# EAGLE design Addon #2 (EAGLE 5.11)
COPYRIGHT: © 2013 Leo-Andres Hofmann; LICENSE: CC-BY-SA 3.0; PROJEKT: miniSTK Addon #2; REVISION: 1.0; TEXT-1: Pin-Breakout, Allgemeines; TEXT-2: Pufferelkos; TEXT-3: Spannungsregler (linear); TEXT-5: Platine: 75mm x 85mm; TP_SIGNAL_NAME: GND

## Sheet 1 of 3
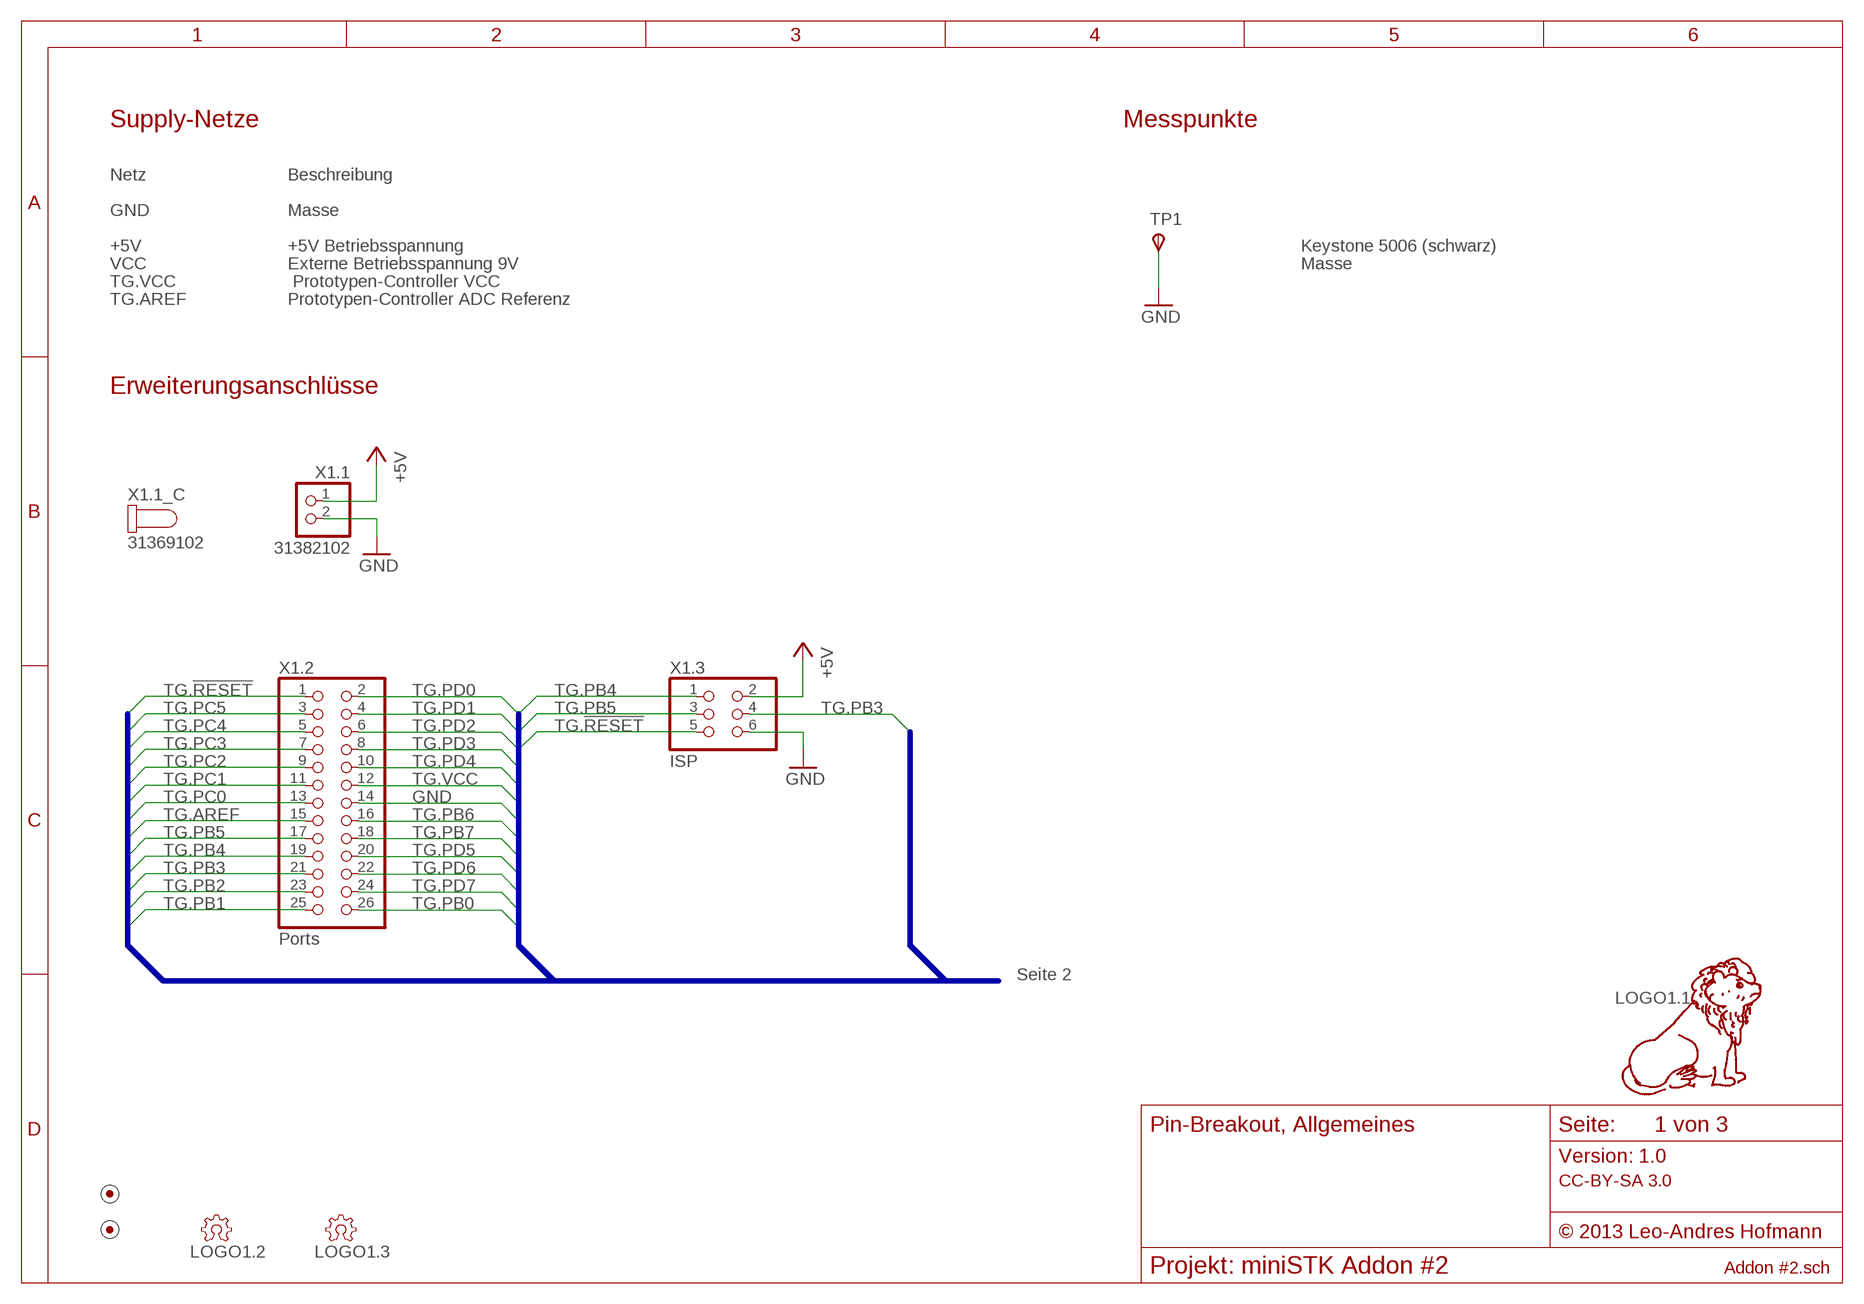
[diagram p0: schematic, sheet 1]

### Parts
LOGO1.1  LOGO-10MM-TPLACE  [10MM-TPLACE]
LOGO1.2  OSHW-3MM-FILL-TPLACE  [OSHW-FILL-3MM-TPLACE]
LOGO1.3  OSHW-3MM-FILL-TSTOP  [OSHW-FILL-3MM-TSTOP]
MARK1  FIDUCIAL-1.0/CREAM  [FIDUCIAL-1MM/CREAM]
MARK2  FIDUCIAL-1.0/CREAM  [FIDUCIAL-1MM/CREAM]
TP1  5006  TESTPOINT-1.6MM  [TESTPOINT-1.6MM]
X1.1  31382102  1PIN-2-31382102  [31382102]
X1.2  Ports  PINHD-2X13  [2X13]
X1.3  ISP  PINHD-2X3  [2X03]

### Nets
+5V: X1.1.1 X1.3.2 ; also sheet 2,3
GND: TP1.TP(PP) X1.1.2 X1.2.14 X1.3.6 ; also sheet 2,3
TG.!RESET: X1.2.1 X1.3.5 ; also sheet 2
TG.AREF: X1.2.15 ; also sheet 2
TG.PB0: X1.2.26 ; also sheet 2
TG.PB1: X1.2.25 ; also sheet 2
TG.PB2: X1.2.23 ; also sheet 2
TG.PB3: X1.2.21 X1.3.4 ; also sheet 2
TG.PB4: X1.2.19 X1.3.1 ; also sheet 2
TG.PB5: X1.2.17 X1.3.3 ; also sheet 2
TG.PB6: X1.2.16 ; also sheet 2
TG.PB7: X1.2.18 ; also sheet 2
TG.PC0: X1.2.13 ; also sheet 2
TG.PC1: X1.2.11 ; also sheet 2
TG.PC2: X1.2.9 ; also sheet 2
TG.PC3: X1.2.7 ; also sheet 2
TG.PC4: X1.2.5 ; also sheet 2
TG.PC5: X1.2.3 ; also sheet 2
TG.PD0: X1.2.2 ; also sheet 2
TG.PD1: X1.2.4 ; also sheet 2
TG.PD2: X1.2.6 ; also sheet 2
TG.PD3: X1.2.8 ; also sheet 2
TG.PD4: X1.2.10 ; also sheet 2
TG.PD5: X1.2.20 ; also sheet 2
TG.PD6: X1.2.22 ; also sheet 2
TG.PD7: X1.2.24 ; also sheet 2
TG.VCC: X1.2.12 ; also sheet 2

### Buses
TG:GND,TG.VCC,TG.!RESET,TG.AREF,TG.PB0,TG.PB1,TG.PB2,TG.PB3,TG.PB4,TG.PB5,TG.PB6,TG.PB7,TG.PC0,TG.PC1,TG.PC2,TG.PC3,TG.PC4,TG.PC5,TG.PD0,TG.PD1,TG.PD2,TG.PD3,TG.PD4,TG.PD5,TG.PD6,TG.PD7

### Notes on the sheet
- Supply-Netze | Messpunkte
- Netz | Beschreibung
- GND | Masse
- +5V | +5V Betriebsspannung | Keystone 5006 (schwarz)
- VCC | Externe Betriebsspannung 9V | Masse
- TG.VCC | Prototypen-Controller VCC
- TG.AREF | Prototypen-Controller ADC Referenz
- Erweiterungsanschlüsse
- Seite 2

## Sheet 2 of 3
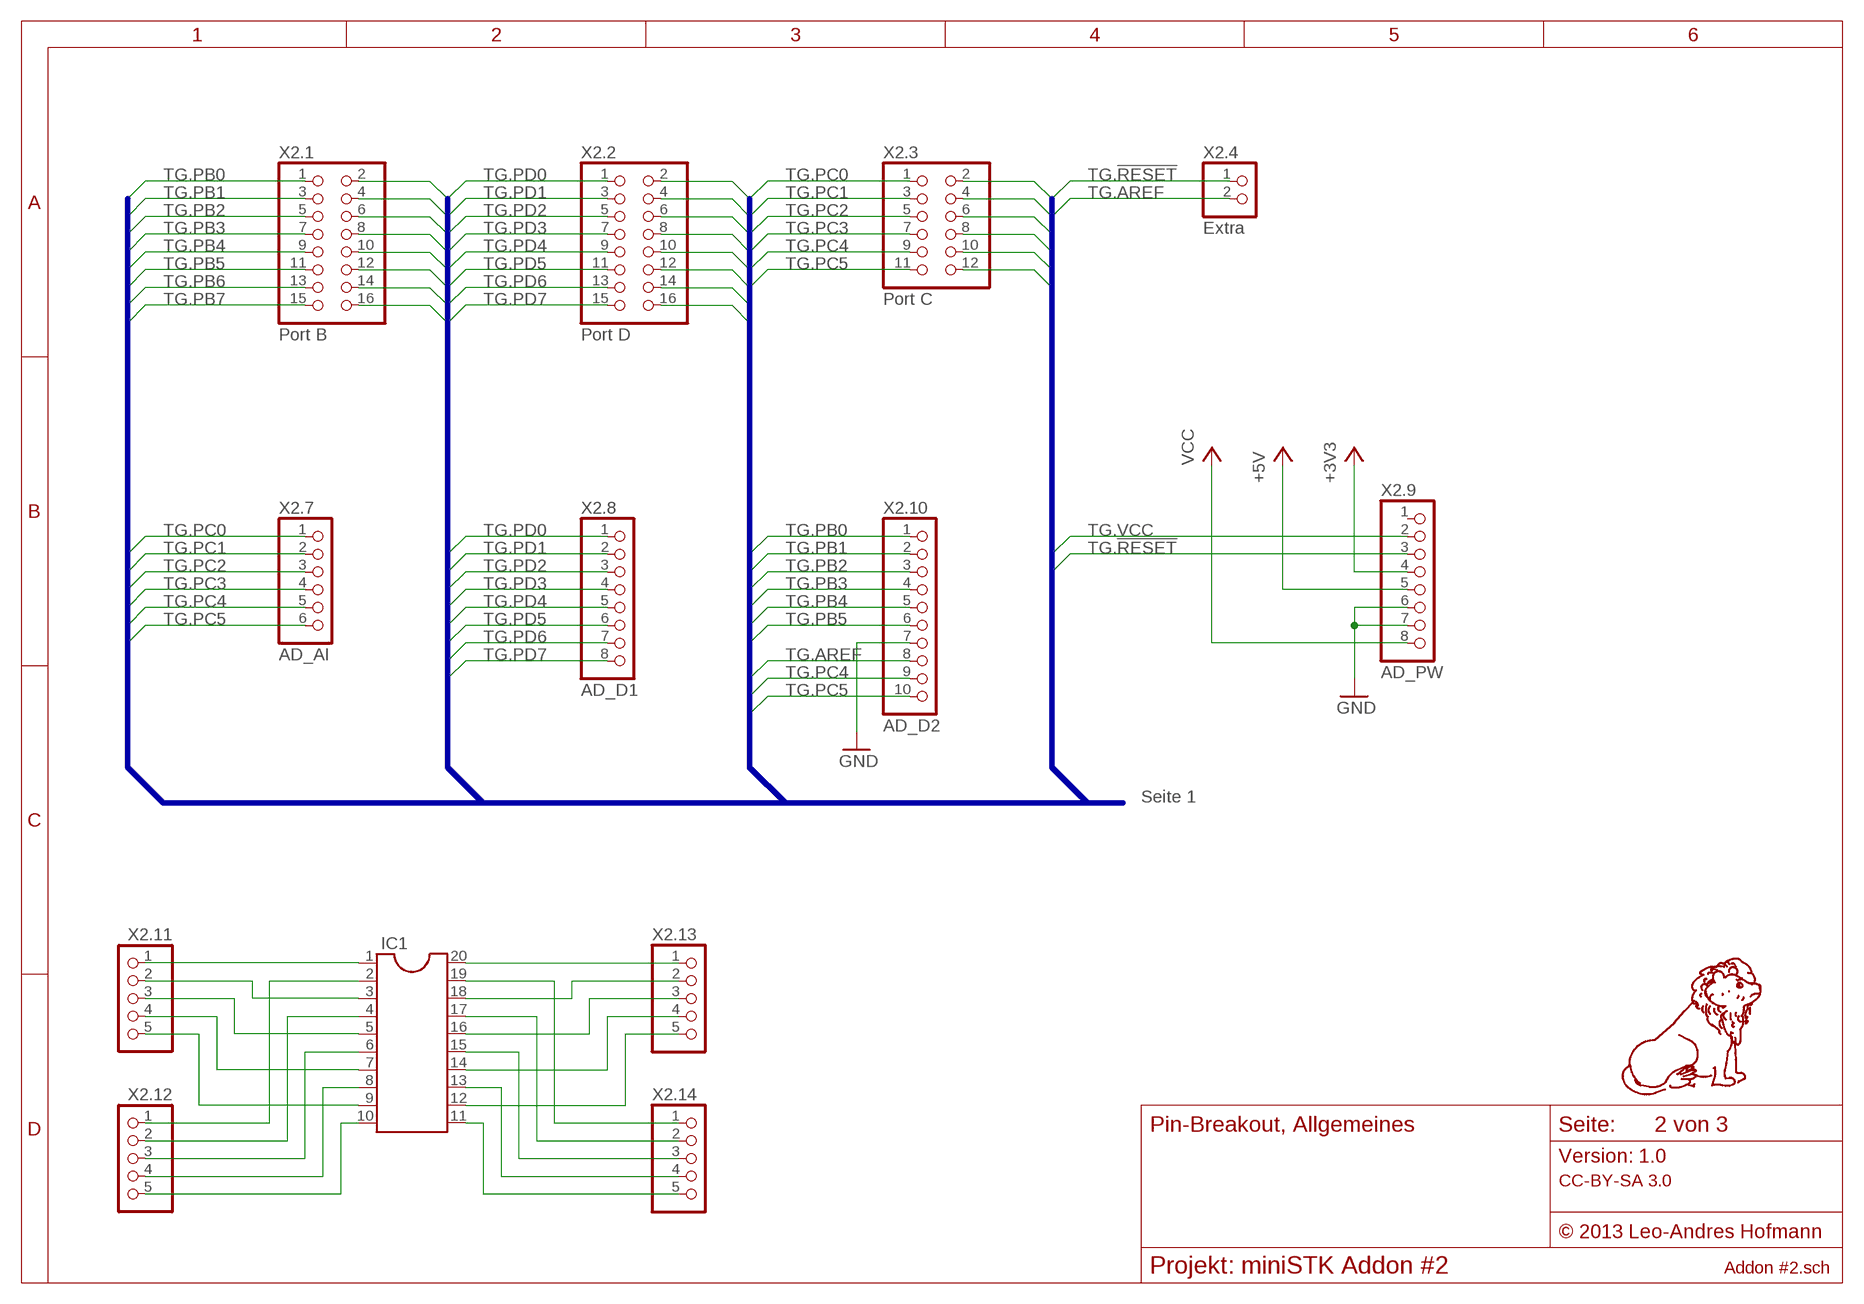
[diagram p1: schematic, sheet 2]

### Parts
IC1  SO-20  [SO-20/MULTI]
X2.1  Port B  PINHD-2X8  [2X08]
X2.2  Port D  PINHD-2X8  [2X08]
X2.3  Port C  PINHD-2X6  [2X06]
X2.4  Extra  PINHD-1X2  [1X02]
X2.7  AD_AI  PINHD-1X6  [1X06]
X2.8  AD_D1  PINHD-1X8  [1X08]
X2.9  AD_PW  PINHD-1X8  [1X08]
X2.10  AD_D2  PINHD-1X10  [1X10]
X2.11  PINHD-1X5  [1X05]
X2.12  PINHD-1X5  [1X05]
X2.13  PINHD-1X5  [1X05]
X2.14  PINHD-1X5  [1X05]

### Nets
+3V3: X2.9.4 ; also sheet 3
+5V: X2.9.5 ; also sheet 1,3
GND: X2.9.6 X2.9.7 X2.10.7 ; also sheet 1,3
N$21: IC1.1 X2.11.1
N$22: IC1.9 X2.11.5
N$23: IC1.7 X2.11.4
N$24: IC1.5 X2.11.3
N$25: IC1.3 X2.11.2
N$26: IC1.10 X2.12.5
N$27: IC1.8 X2.12.4
N$28: IC1.6 X2.12.3
N$29: IC1.4 X2.12.2
N$30: IC1.2 X2.12.1
N$31: IC1.13 X2.14.4
N$32: IC1.15 X2.14.3
N$33: IC1.20 X2.13.1
N$34: IC1.11 X2.14.5
N$35: IC1.17 X2.14.2
N$36: IC1.19 X2.14.1
N$37: IC1.12 X2.13.5
N$38: IC1.18 X2.13.2
N$39: IC1.16 X2.13.3
N$40: IC1.14 X2.13.4
TG.!RESET: X2.4.1 X2.9.3 ; also sheet 1
TG.AREF: X2.4.2 X2.10.8 ; also sheet 1
TG.PB0: X2.1.1 X2.1.2 X2.10.1 ; also sheet 1
TG.PB1: X2.1.3 X2.1.4 X2.10.2 ; also sheet 1
TG.PB2: X2.1.5 X2.1.6 X2.10.3 ; also sheet 1
TG.PB3: X2.1.7 X2.1.8 X2.10.4 ; also sheet 1
TG.PB4: X2.1.9 X2.1.10 X2.10.5 ; also sheet 1
TG.PB5: X2.1.11 X2.1.12 X2.10.6 ; also sheet 1
TG.PB6: X2.1.13 X2.1.14 ; also sheet 1
TG.PB7: X2.1.15 X2.1.16 ; also sheet 1
TG.PC0: X2.3.1 X2.3.2 X2.7.1 ; also sheet 1
TG.PC1: X2.3.3 X2.3.4 X2.7.2 ; also sheet 1
TG.PC2: X2.3.5 X2.3.6 X2.7.3 ; also sheet 1
TG.PC3: X2.3.7 X2.3.8 X2.7.4 ; also sheet 1
TG.PC4: X2.3.9 X2.3.10 X2.7.5 X2.10.9 ; also sheet 1
TG.PC5: X2.3.11 X2.3.12 X2.7.6 X2.10.10 ; also sheet 1
TG.PD0: X2.2.1 X2.2.2 X2.8.1 ; also sheet 1
TG.PD1: X2.2.3 X2.2.4 X2.8.2 ; also sheet 1
TG.PD2: X2.2.5 X2.2.6 X2.8.3 ; also sheet 1
TG.PD3: X2.2.7 X2.2.8 X2.8.4 ; also sheet 1
TG.PD4: X2.2.9 X2.2.10 X2.8.5 ; also sheet 1
TG.PD5: X2.2.11 X2.2.12 X2.8.6 ; also sheet 1
TG.PD6: X2.2.13 X2.2.14 X2.8.7 ; also sheet 1
TG.PD7: X2.2.15 X2.2.16 X2.8.8 ; also sheet 1
TG.VCC: X2.9.2 ; also sheet 1
VCC: X2.9.8 ; also sheet 3
Unconnected: X2.9.1

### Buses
PORTS:TG.VCC,TG.!RESET,TG.AREF,TG.PB0,TG.PB1,TG.PB2,TG.PB3,TG.PB4,TG.PB5,TG.PB6,TG.PB7,TG.PC0,TG.PC1,TG.PC2,TG.PC3,TG.PC4,TG.PC5,TG.PD0,TG.PD1,TG.PD2,TG.PD3,TG.PD4,TG.PD5,TG.PD6,TG.PD7

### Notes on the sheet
- Seite 1

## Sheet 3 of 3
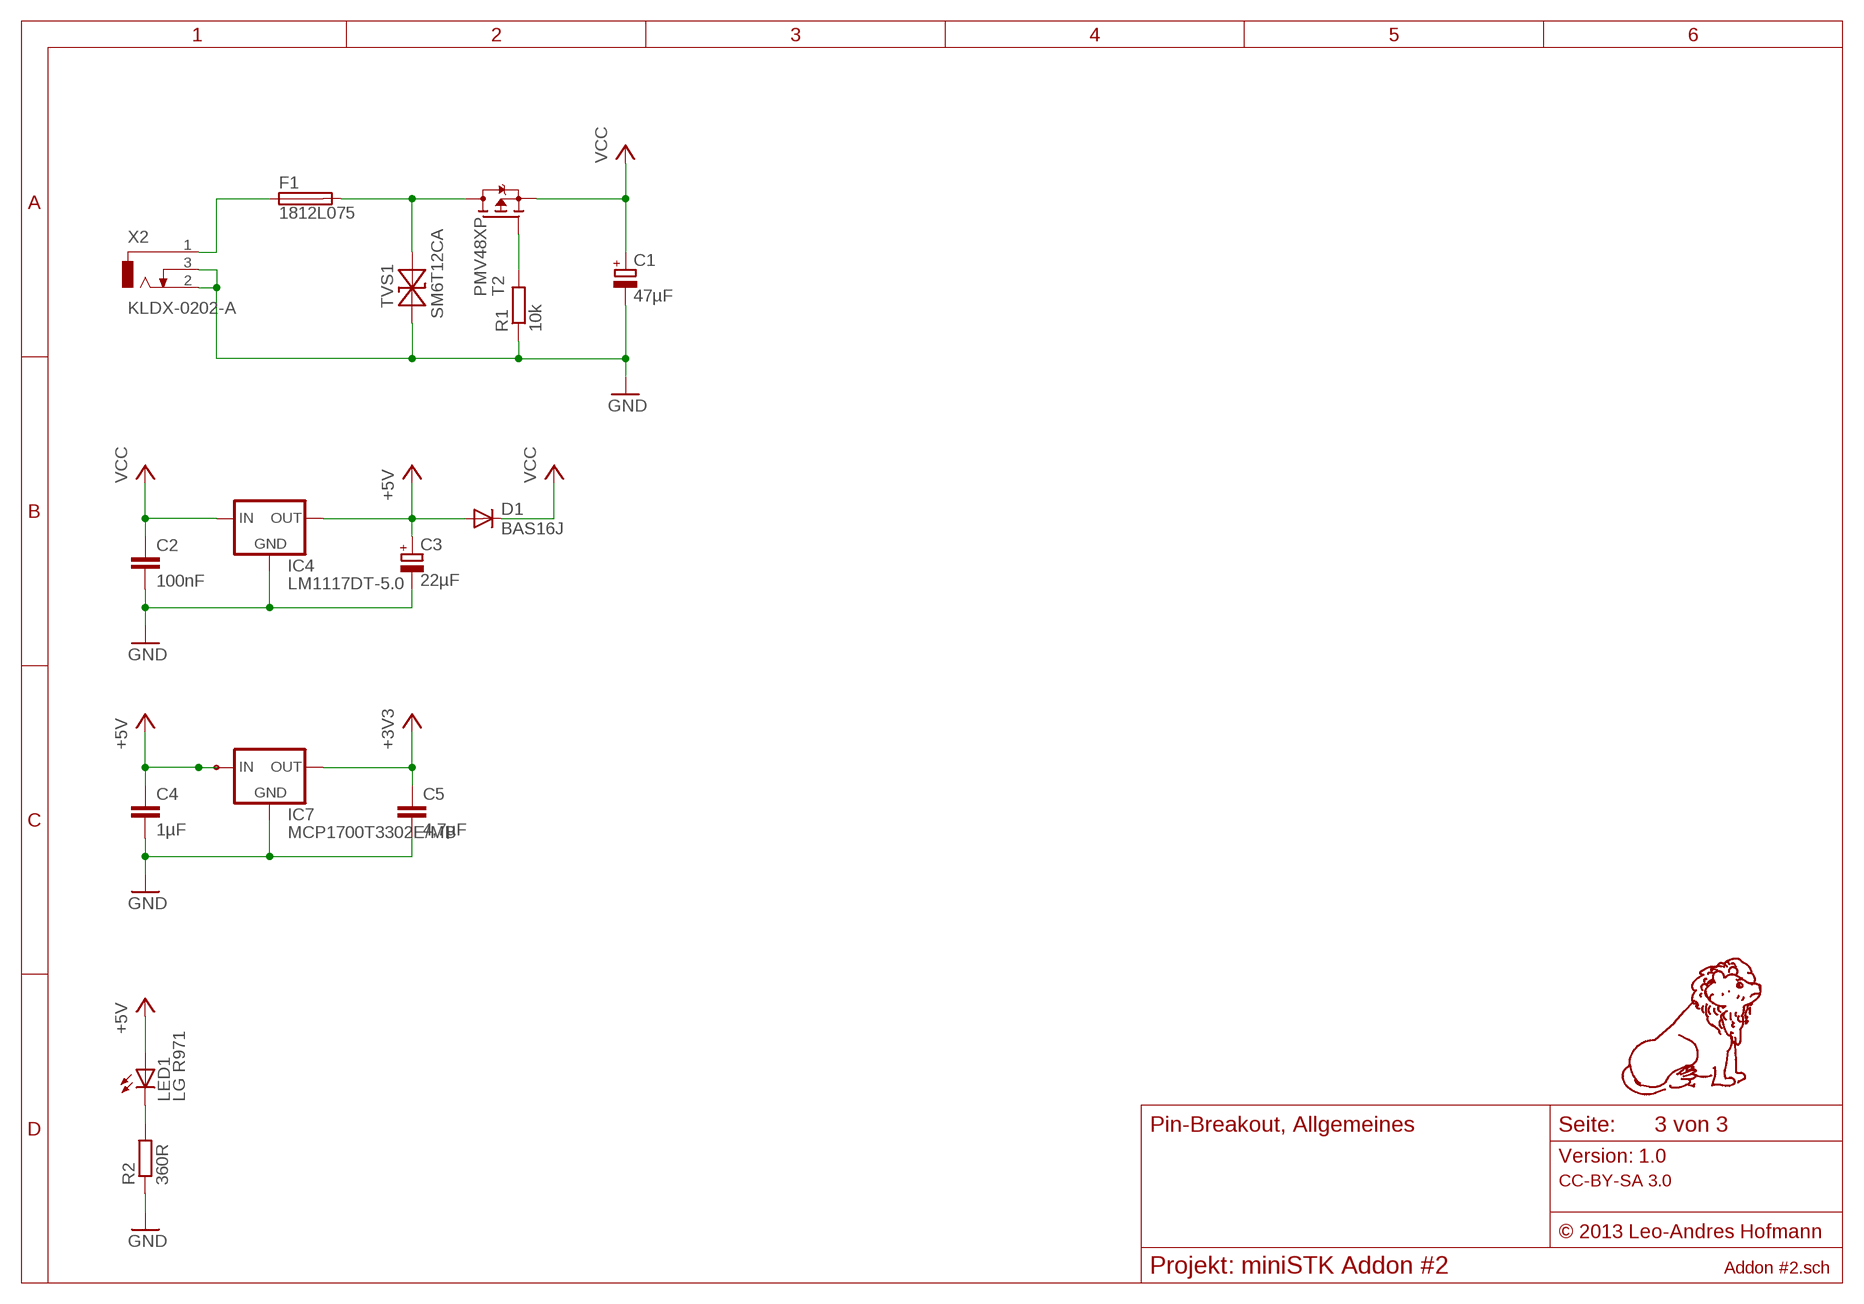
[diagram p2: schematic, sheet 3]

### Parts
C1  47µF  CPOL-EUC  [PANASONIC_C]
C2  100nF  C-0603  [C-0603]
C3  22µF  CPOL-EUB  [PANASONIC_B]
C4  1µF  C-0603  [C-0603]
C5  4,7µF  C-0805  [C-0805]
D1  BAS16J  DIODE-SOD323  [DIODE-SOD323]
F1  1812L075  SMD-FUSE-1812L  [LITTLEFUSE-1812L]
IC4  LM1117DT-5.0  V-REG-FIX/LD1117DT  [DPAK/2]
IC7  MCP1700T3302E/MB  V-REG-FIX-2I/MCP1700  [SOT-89]
LED1  LG R971  LED-CHIPLED-0805  [CHIPLED-0805]
R1  10k  R-0603  [R-0603]
R2  360R  R-0603  [R-0603]
T2  PMV48XP  P-FET-IRLML6402  [SOT-23]
TVS1  SM6T12CA  TVS-BIDI-SM6T-X-CA  [DO214-AA]
X2  KLDX-0202-A  DC-JACK-KLDX  [DC-JACK-KLDX/DRILL]

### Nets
+3V3: C5.1 IC7.3(OUT) ; also sheet 2
+5V: C3.+ C4.1 D1.A IC4.2/TAB(OUT) IC7.2(IN) IC7.2@1(IN) LED1.A ; also sheet 1,2
GND: C1.- C2.2 C3.- C4.2 C5.2 IC4.1(GND) IC7.1(GND) R1.1 R2.1 TVS1.A X2.2(TAB) X2.3(SW) ; also sheet 1,2
N$41: F1.1 X2.1(PIN)
N$43: F1.2 T2.3(D) TVS1.K
N$44: R1.2 T2.1(G)
N$45: LED1.C R2.2
VCC: C1.+ C2.1 D1.C IC4.3(IN) T2.2(S) ; also sheet 2

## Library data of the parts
C1 C3 = rcl:CPOL-EU: POLARIZED CAPACITOR, European symbol
C2 C4 C5 = leo_rc-smd:C: Capacitor
D1 = leo_misc-smd:DIODE: SMD Diode
F1 = leo_fuse-smd:SMD-FUSE: Surface Mount Fuses
IC1 = leo_misc-smd:SO-20: SO-20 wide/small multi-footprint
IC4 = leo_misc-smd:V-REG-FIX: SMD Voltage Regulator, Fixed Output
IC7 = leo_misc-smd:V-REG-FIX-2I: SMD Voltage Regulator, Fixed Output
LED1 = leo_misc-smd:LED: SMD LED
LOGO1.1 = leo_misc-logo:LOGO: leo-andres.de PCB Logo
LOGO1.2 LOGO1.3 = leo_misc-logo:OSHW: OSHW Logo
MARK1 MARK2 = leo_misc-logo:FIDUCIAL: Fiducial
R1 R2 = leo_rc-smd:R: Resistor
T2 = leo_transistor-irf-hexfet:P-FET: P-Channel IRF Hexfet, 3 Lead Package
TP1 = leo_misc-tht:TESTPOINT: Keystone THT Testpoints (wire loop)
TVS1 = leo_diode-tvs:TVS-BIDI: TVS Diode, Bidirectional
X1.1 = leo_con-ria:1PIN-2: 1 Pin Header, 2 Pole
X1.2 = pinhead:PINHD-2X13: PIN HEADER
X1.3 = pinhead:PINHD-2X3: PIN HEADER
X2 = leo_misc-tht:DC-JACK: DC Power Jack "_DB" - Version: Recommended PCB Layout
X2.1 X2.2 = pinhead:PINHD-2X8: PIN HEADER
X2.3 = pinhead:PINHD-2X6: PIN HEADER
X2.4 = pinhead:PINHD-1X2: PIN HEADER
X2.7 = pinhead:PINHD-1X6: PIN HEADER
X2.8 X2.9 = pinhead:PINHD-1X8: PIN HEADER
X2.10 = pinhead:PINHD-1X10: PIN HEADER
X2.11-X2.14 = pinhead:PINHD-1X5: PIN HEADER

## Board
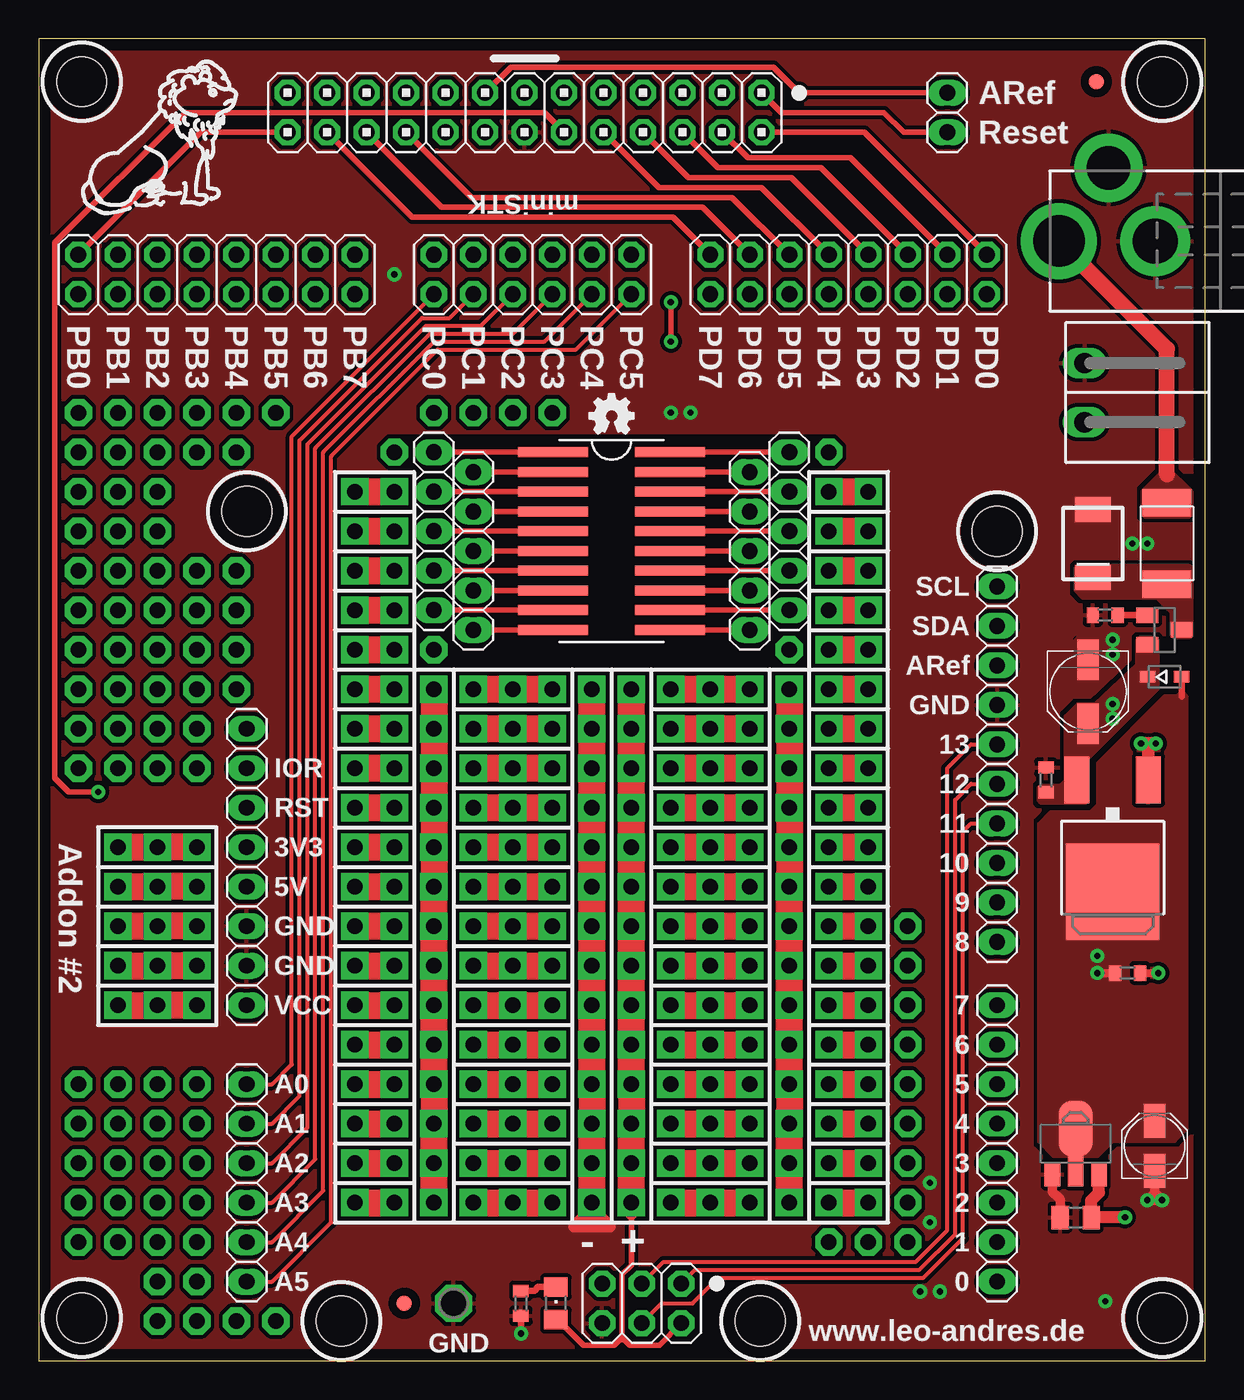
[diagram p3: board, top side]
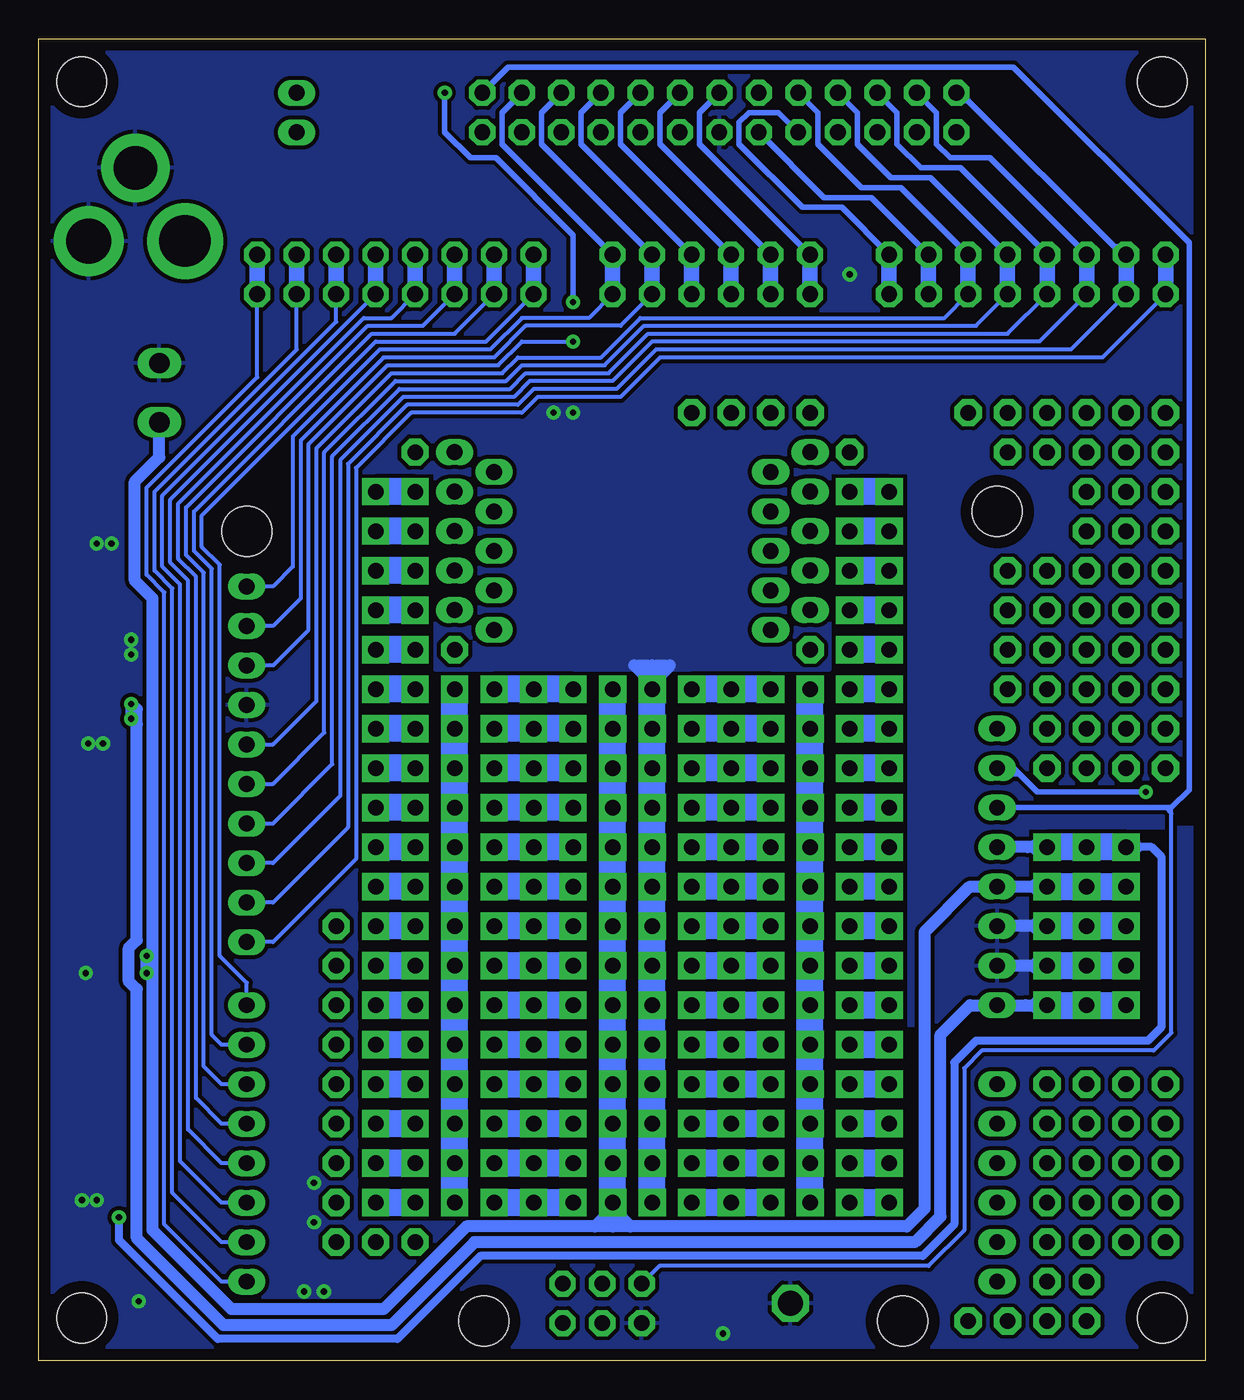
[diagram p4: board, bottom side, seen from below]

Size 75 x 85 mm. Coordinates in mm from the lower left corner, seen from the top.
Outline: 0,0 75,0 75,85 0,85 0,0
Copper layers (1*16): Top 0.035mm / dielectric 1.5mm / Bottom 0.035mm
Design rules "2-Layer 10x10 *": minimum track width 10mil, minimum drill 0.4mm, track to track 10mil, track to pad 10mil, pad to pad 10mil, via to via 10mil, smd to smd 10mil, copper to edge 0.75mm, drill to drill 10mil, minimum pad ring 13mil, minimum via ring 10mil, stop-mask expansion 4mil, vias tented up to drill 0.6mm, thermal gap 10mil

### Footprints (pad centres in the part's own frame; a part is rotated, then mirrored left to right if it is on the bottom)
PANASONIC_C = smd 2.6 x 1.4: + 2.05,0; - -2.05,0
C-0603 = smd 0.8 x 1: 1 -0.8,0; 2 0.8,0
PANASONIC_B = smd 2.2 x 1.4: + 1.6,0; - -1.6,0
C-0805 = smd 1.1 x 1.5: 1 -1,0; 2 1,0
DIODE-SOD323 = smd 1 x 0.75: A 1.1,0; C -1.1,0
LITTLEFUSE-1812L = smd 1.78 x 3.15: 1 -2.615,0; 2 2.615,0
SO-20/MULTI = smd 0.65 x 4.5: 1 -5.715,-3.75; 2 -4.445,-3.75; 3 -3.175,-3.75; 4 -1.905,-3.75; 5 -0.635,-3.75; 6 0.635,-3.75; 7 1.905,-3.75; 8 3.175,-3.75; 9 4.445,-3.75; 10 5.715,-3.75; 11 5.715,3.75; 12 4.445,3.75; 13 3.175,3.75; 14 1.905,3.75; 15 0.635,3.75; 16 -0.635,3.75; 17 -1.905,3.75; 18 -3.175,3.75; 19 -4.445,3.75; 20 -5.715,3.75
DPAK/2 = smd 1.6 x 3: 1 -2.3,-4.8; 3 2.3,-4.8 | smd 6 x 6.2: 2/TAB 0,2.4
SOT-89 = smd 1 x 1.5: 1 -1.5,-2; 3 1.5,-2 | smd 1 x 2.2: 2 0,-1.65 | smd 2.2 x 3.6: 2@1 0,0.95
CHIPLED-0805 = smd 1.25 x 1.5: A 1.05,0; C -1.05,0
FIDUCIAL-1MM/CREAM = smd 1 x 1: FIDUCIAL 0,0
R-0603 = smd 0.8 x 1: 1 -0.8,0; 2 0.8,0
SOT-23 = smd 1 x 1.4: 1 -0.95,-1.1; 2 0.95,-1.1; 3 0,1.1
TESTPOINT-1.6MM = drill 1.6 octagon: TP 0,0
DO214-AA = smd 1.6 x 2.3: A 2.175,0; K -2.175,0
MOUNT-DRILL_3.2 = hole 3.2: 0,0
31382102 = drill 1.3 long: 1 8,1.905; 2 8,-1.905
2X13 = drill 1.016 octagon: 1 -15.24,-1.27; 2 -15.24,1.27; 3 -12.7,-1.27; 4 -12.7,1.27; 5 -10.16,-1.27; 6 -10.16,1.27; 7 -7.62,-1.27; 8 -7.62,1.27; 9 -5.08,-1.27; 10 -5.08,1.27; 11 -2.54,-1.27; 12 -2.54,1.27; 13 0,-1.27; 14 0,1.27; 15 2.54,-1.27; 16 2.54,1.27; 17 5.08,-1.27; 18 5.08,1.27; 19 7.62,-1.27; 20 7.62,1.27; 21 10.16,-1.27; 22 10.16,1.27; 23 12.7,-1.27; 24 12.7,1.27; 25 15.24,-1.27; 26 15.24,1.27
2X03 = drill 1.016 octagon: 1 -2.54,-1.27; 2 -2.54,1.27; 3 0,-1.27; 4 0,1.27; 5 2.54,-1.27; 6 2.54,1.27
DC-JACK-KLDX/DRILL = drill 3.3 pad 4.9 round: 1 13.9,0 | drill 2.9 pad 4.5 round: 2 7.7,0 | drill 2.8 pad 4.4 round: 3 10.7,-4.7
2X08 = drill 1.016 octagon: 1 -8.89,-1.27; 2 -8.89,1.27; 3 -6.35,-1.27; 4 -6.35,1.27; 5 -3.81,-1.27; 6 -3.81,1.27; 7 -1.27,-1.27; 8 -1.27,1.27; 9 1.27,-1.27; 10 1.27,1.27; 11 3.81,-1.27; 12 3.81,1.27; 13 6.35,-1.27; 14 6.35,1.27; 15 8.89,-1.27; 16 8.89,1.27
2X06 = drill 1.016 octagon: 1 -6.35,-1.27; 2 -6.35,1.27; 3 -3.81,-1.27; 4 -3.81,1.27; 5 -1.27,-1.27; 6 -1.27,1.27; 7 1.27,-1.27; 8 1.27,1.27; 9 3.81,-1.27; 10 3.81,1.27; 11 6.35,-1.27; 12 6.35,1.27
1X02 = drill 1.016 long: 1 -1.27,0; 2 1.27,0
1X06 = drill 1.016 long: 1 -6.35,0; 2 -3.81,0; 3 -1.27,0; 4 1.27,0; 5 3.81,0; 6 6.35,0
1X08 = drill 1.016 long: 1 -8.89,0; 2 -6.35,0; 3 -3.81,0; 4 -1.27,0; 5 1.27,0; 6 3.81,0; 7 6.35,0; 8 8.89,0
1X10 = drill 1.016 long: 1 -11.43,0; 2 -8.89,0; 3 -6.35,0; 4 -3.81,0; 5 -1.27,0; 6 1.27,0; 7 3.81,0; 8 6.35,0; 9 8.89,0; 10 11.43,0
1X05 = drill 1.016 long: 1 -5.08,0; 2 -2.54,0; 3 0,0; 4 2.54,0; 5 5.08,0

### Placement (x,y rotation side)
C1  67.47,43.02 270 top
C2  64.77,37.34 90 top
C3  71.75,13.81 90 top
C4  70.01,24.92 0 top
C5  66.67,9.21 180 top
D1  72.39,43.97 0 top
F1  72.55,52.55 270 top
IC1  36.83,52.7 270 top
IC4  69.06,32.54 180 top
IC7  66.68,13.97 0 top
LED1  33.25,3.68 270 top
LOGO1.1  7.75,78.75 0 top
LOGO1.2  36.83,60.9 0 top
LOGO1.3  36.83,54 0 bottom
MARK1  23.5,3.68 0 top
MARK2  68,82.25 0 top
R1  68.58,47.94 0 top
R2  31,3.68 90 top
T2  72.39,46.99 270 top
TP1  26.67,3.68 0 top
TVS1  67.79,52.55 90 top
U$1  [MOUNT-DRILL_3.2]  2.75,2.75 0 top
U$2  [MOUNT-DRILL_3.2]  72.25,2.75 0 top
U$3  [MOUNT-DRILL_3.2]  72.25,82.25 0 top
U$4  [MOUNT-DRILL_3.2]  2.75,82.25 0 top
U$5  [MOUNT-DRILL_3.2]  19.45,2.54 0 top
U$6  [MOUNT-DRILL_3.2]  46.39,2.54 0 top
U$7  [MOUNT-DRILL_3.2]  61.63,53.34 0 top
U$8  [MOUNT-DRILL_3.2]  13.37,54.61 0 top
X1.1  75.25,62.25 180 top
X1.2  31.24,80.26 180 top
X1.3  38.77,3.68 180 top
X2  79.5,72 180 top
X2.1  11.43,69.85 0 top
X2.2  52.07,69.85 180 top
X2.3  31.75,69.85 0 top
X2.4  58.42,80.26 90 top
X2.7  13.37,11.43 270 top
X2.8  61.63,13.97 90 top
X2.9  13.37,31.75 270 top
X2.10  61.63,38.35 90 top
X2.11  25.4,53.34 270 top
X2.12  27.94,52.07 270 top
X2.13  48.26,53.34 270 top
X2.14  45.72,52.07 270 top

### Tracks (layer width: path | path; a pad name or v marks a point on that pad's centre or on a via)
+3V3  (via drill 0.4, 1 pad 1.75)
  Top 0.762: IC7.3 68.17,10.79 67.67,10.29 C5.1 v69.85,9.21
  Top 1.75: v5.08,33.02 v7.62,33.02 v10.16,33.02
  Bottom 0.508: v69.85,9.21 69.85,7.75 63.5,1.4 51.94,1.4 46.61,6.73 18.16,6.73 16.13,8.76 16.13,19.18 14.73,20.57 3.68,20.57 2.79,21.46 2.79,32.38 3.43,33.02 4.19,33.02 | 4.19,33.02 v5.08,33.02 | 4.19,33.02 4.57,33.4 | 4.19,33.02 4.57,32.64
  Bottom 0.762: v10.16,33.02 11.05,33.02 | X2.9.4 11.43,33.02 11.05,33.02 | 11.05,33.02 10.67,33.4 | 11.05,33.02 10.67,32.64
  Bottom 1.75: v5.08,33.02 v10.16,33.02
+5V  (via drill 0.4, 1 pad 1.75)
  Top 0.35: LED1.A 33.4,2.63 35.04,1 37,1 37.33,1.33 | v38.1,10.16 38.1,9.14 | X1.3.2 39.9,1 38,1 37.67,1.33 | 37.5,1.5 37.67,1.33 | 37.5,1.5 37.33,1.33 | 37.67,1.33 37.33,1.33 | 37.5,1.5 37.5,5.54 38.1,6.14 38.1,9.14 | 38.1,9.14 37.59,9.65 | 38.1,9.14 38.61,9.65
  Top 0.406: 73.49,42.72 D1.A
  Top 0.508: IC7.2 IC7.2@1 | v68.07,24.92 C4.1
  Top 1.75: v38.1,43.18 v38.1,40.64 v38.1,38.1 v38.1,35.56 v38.1,33.02 v38.1,30.48 v38.1,27.94 v38.1,25.4 v38.1,22.86 v38.1,20.32 v38.1,17.78 v38.1,15.24 v38.1,12.7 v38.1,10.16 | v5.08,30.48 v7.62,30.48 v10.16,30.48
  Bottom 0.762: X1.1.1 67.25,58.1 68.83,56.52 68.83,50.16 67.69,49.02 67.69,26.42 | 67.69,26.42 v68.07,26.04 v68.07,24.92 | 67.69,25.3 67.69,26.42 | 67.69,25.3 v68.07,24.92 | 11.05,30.48 v10.16,30.48 | 36.96,8.64 19.18,8.64 18.03,9.78 18.03,27.56 15.11,30.48 X2.9.5 11.05,30.48 | 36.96,8.64 38.1,8.64 | 38.1,8.64 39.24,8.64 | 67.69,24.54 67.69,25.3 | 67.69,24.54 67.69,8.38 62.61,3.3 52.83,3.3 47.5,8.64 39.24,8.64 | 67.69,24.54 v68.07,24.92 | 38.1,8.64 38.1,9.78 | 38.1,9.78 v38.1,10.16 | 36.96,8.64 38.1,9.78 | 38.1,9.78 39.24,8.64 | 11.05,30.48 10.67,30.86 | 11.05,30.48 10.67,30.1
  Bottom 1.75: v38.1,43.18 v38.1,40.64 v38.1,38.1 v38.1,35.56 v38.1,33.02 v38.1,30.48 v38.1,27.94 v38.1,25.4 v38.1,22.86 v38.1,20.32 v38.1,17.78 v38.1,10.16 | v10.16,30.48 v5.08,30.48
  pour Top (rank 3, no thermals): 73.82,14.92 73.82,42.7 73.5,43.02 73.18,42.7 72.39,42.7 68.1,38.42 68.1,35.72 67.63,35.24 65.06,35.24 64.29,34.48 64.29,14.13 65.25,13.18 68.1,13.18 69.06,14.13 73.03,14.13
GND  (via drill 0.4, 1 pad 1.75)
  Top 0.406: v31,1.75 R2.1
  Top 0.508: C4.2 v71.99,24.92
  Top 0.61: C3.- 71.75,10.79 | 71.75,10.79 v72.23,10.32 v71.28,10.32 71.75,10.79 | 71.75,10.79 | C5.2 65.67,10.37 65.17,10.87 IC7.1
  Top 0.762: 35.56,9.78 36.7,8.64 35.56,8.64 | 35.56,9.78 v35.56,10.16 35.56,8.64 | 35.56,9.78 34.42,8.64 35.56,8.64
  Top 0.813: IC4.1 71.36,39.69 | 71.36,39.69 v71.83,39.69 | 71.36,39.69 v70.88,39.69
  Top 1.75: v35.56,43.18 v35.56,40.64 v35.56,38.1 v35.56,35.56 v35.56,33.02 v35.56,30.48 v35.56,27.94 v35.56,25.4 v35.56,22.86 v35.56,20.32 v35.56,17.78 v35.56,15.24 v35.56,12.7 v35.56,10.16 | v5.08,27.94 v7.62,27.94 v10.16,27.94 | v5.08,25.4 v7.62,25.4 v10.16,25.4
  Bottom 0.762: v10.16,27.94 11.05,27.94 | v10.16,25.4 11.05,25.4 | 35.56,43.56 35.56,44.7 | 35.56,43.56 36.7,44.7 34.42,44.7 35.56,43.56 | v35.56,43.18 35.56,43.56 | 11.05,27.94 10.67,28.32 | 11.05,27.94 X2.9.6 | 11.05,27.94 10.67,27.56 | 11.05,25.4 10.67,25.78 | 11.05,25.4 X2.9.7 | 11.05,25.4 10.67,25.02
  Bottom 1.75: v35.56,43.18 v35.56,40.64 v35.56,38.1 v35.56,35.56 v35.56,33.02 v35.56,30.48 v35.56,27.94 v35.56,25.4 v35.56,22.86 v35.56,20.32 v35.56,17.78 v35.56,10.16 | v5.08,27.94 v10.16,27.94 | v5.08,25.4 v10.16,25.4
  other vias: 22.86,69.85 69.06,46.36 70.33,52.55 69.06,45.4 71.28,52.55 68.58,3.81 57.31,8.89 41.91,60.96 40.64,60.96 57.94,4.45 57.31,11.43 56.67,4.45
  pour Top (rank 2, no thermals): 66.67,55.72 68.9,55.72 71.75,52.86 71.75,52.39 71.44,52.07 70.07,52.07 68.48,53.66 66.68,53.66 66.36,53.98 66.36,55.4
  pour Top (rank 2, no thermals): 66.83,43.5 68.1,43.5 69.53,45.09 69.53,46.51 69.22,46.83 68.9,46.83 68.58,46.51 66.83,46.51 66.52,46.2 66.52,43.81
  pour Top (rank 4, no thermals): 72.55,13.65 72.87,13.34 72.87,10.32 72.55,10 70.96,10 70.64,10.32 70.64,13.34 70.96,13.65
  pour Top (rank 6): 54.61,57.15 75,57.15 75,0 0,0 0,34.29 3.81,34.29 3.81,21.59 19.05,21.59 19.05,8.89 54.61,8.89
  pour Top (rank 6): 0,85 75,85 75,57.15 51.31,57.15 50.8,57.66 50.8,59.69 22.86,59.69 22.86,57.66 22.35,57.15 19.05,57.15 19.05,21.59 11.43,21.59 11.43,34.29 0,34.29
  pour Bottom (rank 6): 75,57.15 49.53,57.15 49.53,44.45 24.13,44.45 24.13,57.15 19.05,57.15 19.05,21.59 11.43,21.59 11.43,34.29 0,34.29 0,85 75,85
  pour Bottom (rank 6): 75,0 75,57.15 54.61,57.15 54.61,8.89 19.05,8.89 19.05,21.59 3.81,21.59 3.81,34.29 0,34.29 0,0
N$1  (via drill 1 pad 1.75)
  Top 1.75: v40.64,17.78 v43.18,17.78 v45.72,17.78
  Bottom 1.75: v40.64,17.78 v45.72,17.78
N$2  (via drill 1 pad 1.75)
  Top 1.75: v40.64,20.32 v43.18,20.32 v45.72,20.32
  Bottom 1.75: v40.64,20.32 v45.72,20.32
N$3  (via drill 1 pad 1.75)
  Top 1.75: v40.64,22.86 v43.18,22.86 v45.72,22.86
  Bottom 1.75: v40.64,22.86 v45.72,22.86
N$4  (via drill 1 pad 1.75)
  Top 1.75: v40.64,25.4 v43.18,25.4 v45.72,25.4
  Bottom 1.75: v40.64,25.4 v43.18,25.4 v45.72,25.4
N$5  (via drill 1 pad 1.75)
  Top 1.75: v45.72,27.94 v43.18,27.94 v40.64,27.94
  Bottom 1.75: v40.64,27.94 v43.18,27.94 v45.72,27.94
N$6  (via drill 1 pad 1.75)
  Top 1.75: v45.72,30.48 v43.18,30.48 v40.64,30.48
  Bottom 1.75: v40.64,30.48 v43.18,30.48 v45.72,30.48
N$7  (via drill 1 pad 1.75)
  Top 1.75: v40.64,33.02 v43.18,33.02 v45.72,33.02
  Bottom 1.75: v40.64,33.02 v43.18,33.02 v45.72,33.02
N$8  (via drill 1 pad 1.75)
  Top 1.75: v40.64,35.56 v43.18,35.56 v45.72,35.56
  Bottom 1.75: v40.64,35.56 v43.18,35.56 v45.72,35.56
N$9  (via drill 1 pad 1.75)
  Top 1.75: v45.72,38.1 v43.18,38.1 v40.64,38.1
  Bottom 1.75: v40.64,38.1 v43.18,38.1 v45.72,38.1
N$10  (via drill 1 pad 1.75)
  Top 1.75: v40.64,40.64 v43.18,40.64 v45.72,40.64
  Bottom 1.75: v40.64,40.64 v43.18,40.64 v45.72,40.64
N$11  (via drill 1 pad 1.75)
  Top 1.75: v27.94,17.78 v30.48,17.78 v33.02,17.78
  Bottom 1.75: v27.94,17.78 v30.48,17.78 v33.02,17.78
N$12  (via drill 1 pad 1.75)
  Top 1.75: v27.94,20.32 v30.48,20.32 v33.02,20.32
  Bottom 1.75: v33.02,20.32 v30.48,20.32 v27.94,20.32
N$13  (via drill 1 pad 1.75)
  Top 1.75: v27.94,22.86 v30.48,22.86 v33.02,22.86
  Bottom 1.75: v27.94,22.86 v30.48,22.86 v33.02,22.86
N$14  (via drill 1 pad 1.75)
  Top 1.75: v33.02,25.4 v30.48,25.4 v27.94,25.4
  Bottom 1.75: v33.02,25.4 v30.48,25.4 v27.94,25.4
N$15  (via drill 1 pad 1.75)
  Top 1.75: v33.02,27.94 v30.48,27.94 v27.94,27.94
  Bottom 1.75: v27.94,27.94 v30.48,27.94 v33.02,27.94
N$16  (via drill 1 pad 1.75)
  Top 1.75: v27.94,30.48 v30.48,30.48 v33.02,30.48
  Bottom 1.75: v33.02,30.48 v30.48,30.48 v27.94,30.48
N$17  (via drill 1 pad 1.75)
  Top 1.75: v27.94,33.02 v30.48,33.02 v33.02,33.02
  Bottom 1.75: v27.94,33.02 v30.48,33.02 v33.02,33.02
N$18  (via drill 1 pad 1.75)
  Top 1.75: v33.02,35.56 v30.48,35.56 v27.94,35.56
  Bottom 1.75: v27.94,35.56 v30.48,35.56 v33.02,35.56
N$19  (via drill 1 pad 1.75)
  Top 1.75: v27.94,38.1 v30.48,38.1 v33.02,38.1
  Bottom 1.75: v27.94,38.1 v30.48,38.1 v33.02,38.1
N$20  (via drill 1 pad 1.75)
  Top 1.75: v33.02,40.64 v30.48,40.64 v27.94,40.64
  Bottom 1.75: v27.94,40.64 v30.48,40.64 v33.02,40.64
N$21
  Top 0.35: X2.11.1 IC1.1
N$22
  Top 0.35: X2.11.5 IC1.9
N$23
  Top 0.35: X2.11.4 IC1.7
N$24
  Top 0.35: X2.11.3 IC1.5
N$25
  Top 0.35: X2.11.2 IC1.3
N$26
  Top 0.35: X2.12.5 IC1.10
N$27
  Top 0.35: X2.12.4 IC1.8
N$28
  Top 0.35: X2.12.3 IC1.6
N$29
  Top 0.35: X2.12.2 IC1.4
N$30
  Top 0.35: X2.12.1 IC1.2
N$31
  Top 0.35: IC1.13 X2.14.4
N$32
  Top 0.35: IC1.15 X2.14.3
N$33
  Top 0.35: IC1.20 X2.13.1
N$34
  Top 0.35: IC1.11 X2.14.5
N$35
  Top 0.35: IC1.17 X2.14.2
N$36
  Top 0.35: IC1.19 X2.14.1
N$37
  Top 0.35: IC1.12 X2.13.5
N$38
  Top 0.35: IC1.18 X2.13.2
N$39
  Top 0.35: IC1.16 X2.13.3
N$40
  Top 0.35: IC1.14 X2.13.4
N$41
  Top 1.016: 72.55,56.99 72.55,65.05 X2.1
  pour Top (no thermals): 74.14,54.45 74.14,55.88 72.55,57.47 70.96,55.88 70.96,54.45 71.12,54.29 73.98,54.29
N$42  (via drill 1 pad 1.75)
  Top 1.75: v25.4,43.18 v25.4,40.64 v25.4,38.1 v25.4,35.56 v25.4,33.02 v25.4,30.48 v25.4,27.94 v25.4,25.4 v25.4,22.86 v25.4,20.32 v25.4,17.78 v25.4,15.24 v25.4,12.7 v25.4,10.16
  Bottom 1.75: v25.4,43.18 v25.4,17.78 v25.4,10.16
N$43
  pour Top (no thermals): 73.98,51.12 74.14,50.96 74.14,46.67 73.98,46.51 73.03,46.51 72.87,46.67 72.87,48.1 71.91,49.05 67.15,49.05 66.67,49.53 66.67,50.96 66.83,51.12
N$44
  Top 0.406: R1.2 T2.1
N$45
  Top 0.406: LED1.C 32.12,4.73 31.87,4.48 R2.2
N$46  (via drill 1 pad 1.75)
  Top 1.75: v20.32,55.88 v22.86,55.88
  Bottom 1.75: v20.32,55.88 v22.86,55.88
N$47  (via drill 1 pad 1.75)
  Top 1.75: v20.32,53.34 v22.86,53.34
  Bottom 1.75: v20.32,53.34 v22.86,53.34
N$48  (via drill 1 pad 1.75)
  Top 1.75: v20.32,50.8 v22.86,50.8
  Bottom 1.75: v20.32,50.8 v22.86,50.8
N$49  (via drill 1 pad 1.75)
  Top 1.75: v20.32,48.26 v22.86,48.26
  Bottom 1.75: v20.32,48.26 v22.86,48.26
N$50  (via drill 1 pad 1.75)
  Top 1.75: v20.32,45.72 v22.86,45.72
  Bottom 1.75: v20.32,45.72 v22.86,45.72
N$51  (via drill 1 pad 1.75)
  Top 1.75: v20.32,43.18 v22.86,43.18
  Bottom 1.75: v20.32,43.18 v22.86,43.18
N$52  (via drill 1 pad 1.75)
  Top 1.75: v20.32,40.64 v22.86,40.64
  Bottom 1.75: v20.32,40.64 v22.86,40.64
N$53  (via drill 1 pad 1.75)
  Top 1.75: v20.32,38.1 v22.86,38.1
  Bottom 1.75: v20.32,38.1 v22.86,38.1
N$54  (via drill 1 pad 1.75)
  Top 1.75: v20.32,35.56 v22.86,35.56
  Bottom 1.75: v20.32,35.56 v22.86,35.56
N$55  (via drill 1 pad 1.75)
  Top 1.75: v20.32,33.02 v22.86,33.02
  Bottom 1.75: v20.32,33.02 v22.86,33.02
N$56  (via drill 1 pad 1.75)
  Top 1.75: v48.26,43.18 v48.26,40.64 v48.26,38.1 v48.26,35.56 v48.26,33.02 v48.26,30.48 v48.26,27.94 v48.26,25.4 v48.26,22.86 v48.26,20.32 v48.26,17.78 v48.26,15.24 v48.26,12.7 v48.26,10.16
  Bottom 1.75: v48.26,43.18 v48.26,17.78 v48.26,10.16
N$57  (via drill 1 pad 1.75)
  Top 1.75: v50.8,55.88 v53.34,55.88
  Bottom 1.75: v50.8,55.88 v53.34,55.88
N$58  (via drill 1 pad 1.75)
  Top 1.75: v50.8,53.34 v53.34,53.34
  Bottom 1.75: v50.8,53.34 v53.34,53.34
N$59  (via drill 1 pad 1.75)
  Top 1.75: v50.8,50.8 v53.34,50.8
  Bottom 1.75: v50.8,50.8 v53.34,50.8
N$60  (via drill 1 pad 1.75)
  Top 1.75: v50.8,48.26 v53.34,48.26
  Bottom 1.75: v50.8,48.26 v53.34,48.26
N$61  (via drill 1 pad 1.75)
  Top 1.75: v50.8,45.72 v53.34,45.72
  Bottom 1.75: v50.8,45.72 v53.34,45.72
N$62  (via drill 1 pad 1.75)
  Top 1.75: v50.8,43.18 v53.34,43.18
  Bottom 1.75: v50.8,43.18 v53.34,43.18
N$63  (via drill 1 pad 1.75)
  Top 1.75: v50.8,40.64 v53.34,40.64
  Bottom 1.75: v50.8,40.64 v53.34,40.64
N$64  (via drill 1 pad 1.75)
  Top 1.75: v50.8,38.1 v53.34,38.1
  Bottom 1.75: v50.8,38.1 v53.34,38.1
N$65  (via drill 1 pad 1.75)
  Top 1.75: v50.8,35.56 v53.34,35.56
  Bottom 1.75: v50.8,35.56 v53.34,35.56
N$66  (via drill 1 pad 1.75)
  Top 1.75: v50.8,33.02 v53.34,33.02
  Bottom 1.75: v50.8,33.02 v53.34,33.02
N$67  (via drill 1 pad 1.75)
  Top 1.75: v45.72,43.18 v43.18,43.18 v40.64,43.18
  Bottom 1.75: v40.64,43.18 v45.72,43.18
N$68  (via drill 1 pad 1.75)
  Top 1.75: v27.94,43.18 v30.48,43.18 v33.02,43.18
  Bottom 1.75: v27.94,43.18 v33.02,43.18
N$69  (via drill 1 pad 1.75)
  other vias: 22.86,58.42
N$70  (via drill 1 pad 1.75)
  other vias: 50.8,58.42
N$71  (via drill 1 pad 1.75)
  Top 1.75: v27.94,15.24 v30.48,15.24 v33.02,15.24
  Bottom 1.75: v27.94,15.24 v33.02,15.24
N$72  (via drill 1 pad 1.75)
  Top 1.75: v33.02,12.7 v30.48,12.7 v27.94,12.7
  Bottom 1.75: v27.94,12.7 v33.02,12.7
N$73  (via drill 1 pad 1.75)
  Top 1.75: v27.94,10.16 v30.48,10.16 v33.02,10.16
  Bottom 1.75: v27.94,10.16 v33.02,10.16
N$74  (via drill 1 pad 1.75)
  other vias: 5.08,40.64
N$75  (via drill 1 pad 1.75)
  Top 1.75: v40.64,15.24 v43.18,15.24 v45.72,15.24
  Bottom 1.75: v40.64,15.24 v45.72,15.24
N$76  (via drill 1 pad 1.75)
  Top 1.75: v40.64,12.7 v43.18,12.7 v45.72,12.7
  Bottom 1.75: v40.64,12.7 v45.72,12.7
N$77  (via drill 1 pad 1.75)
  Top 1.75: v40.64,10.16 v43.18,10.16 v45.72,10.16
  Bottom 1.75: v40.64,10.16 v45.72,10.16
N$78  (via drill 1 pad 1.75)
  other vias: 2.54,40.64
N$79  (via drill 1 pad 1.75)
  Top 1.75: v50.8,30.48 v53.34,30.48
  Bottom 1.75: v50.8,30.48 v53.34,30.48
N$80  (via drill 1 pad 1.75)
  Top 1.75: v50.8,27.94 v53.34,27.94
  Bottom 1.75: v50.8,27.94 v53.34,27.94
N$81  (via drill 1 pad 1.75)
  Top 1.75: v50.8,25.4 v53.34,25.4
  Bottom 1.75: v50.8,25.4 v53.34,25.4
N$82  (via drill 1 pad 1.75)
  Top 1.75: v50.8,22.86 v53.34,22.86
  Bottom 1.75: v50.8,22.86 v53.34,22.86
N$83  (via drill 1 pad 1.75)
  Top 1.75: v20.32,30.48 v22.86,30.48
  Bottom 1.75: v20.32,30.48 v22.86,30.48
N$84  (via drill 1 pad 1.75)
  Top 1.75: v20.32,27.94 v22.86,27.94
  Bottom 1.75: v20.32,27.94 v22.86,27.94
N$85  (via drill 1 pad 1.75)
  Top 1.75: v20.32,25.4 v22.86,25.4
  Bottom 1.75: v20.32,25.4 v22.86,25.4
N$86  (via drill 1 pad 1.75)
  Top 1.75: v20.32,22.86 v22.86,22.86
  Bottom 1.75: v20.32,22.86 v22.86,22.86
N$87  (via drill 1 pad 1.75)
  Top 1.75: v20.32,20.32 v22.86,20.32
  Bottom 1.75: v20.32,20.32 v22.86,20.32
N$88  (via drill 1 pad 1.75)
  Top 1.75: v20.32,17.78 v22.86,17.78
  Bottom 1.75: v20.32,17.78 v22.86,17.78
N$89  (via drill 1 pad 1.75)
  Top 1.75: v20.32,15.24 v22.86,15.24
  Bottom 1.75: v20.32,15.24 v22.86,15.24
N$90  (via drill 1 pad 1.75)
  Top 1.75: v20.32,12.7 v22.86,12.7
  Bottom 1.75: v20.32,12.7 v22.86,12.7
N$91  (via drill 1 pad 1.75)
  Top 1.75: v20.32,10.16 v22.86,10.16
  Bottom 1.75: v20.32,10.16 v22.86,10.16
N$92  (via drill 1 pad 1.75)
  Top 1.75: v50.8,20.32 v53.34,20.32
  Bottom 1.75: v50.8,20.32 v53.34,20.32
N$93  (via drill 1 pad 1.75)
  Top 1.75: v50.8,17.78 v53.34,17.78
  Bottom 1.75: v50.8,17.78 v53.34,17.78
N$94  (via drill 1 pad 1.75)
  Top 1.75: v50.8,15.24 v53.34,15.24
  Bottom 1.75: v50.8,15.24 v53.34,15.24
N$95  (via drill 1 pad 1.75)
  Top 1.75: v50.8,12.7 v53.34,12.7
  Bottom 1.75: v50.8,12.7 v53.34,12.7
N$96  (via drill 1 pad 1.75)
  Top 1.75: v50.8,10.16 v53.34,10.16
  Bottom 1.75: v50.8,10.16 v53.34,10.16
N$97  (via drill 1 pad 1.75)
  other vias: 2.54,43.18
N$98  (via drill 1 pad 1.75)
  other vias: 2.54,45.72
N$99  (via drill 1 pad 1.75)
  other vias: 25.4,45.72
N$100  (via drill 1 pad 1.75)
  other vias: 48.26,45.72
N$101  (via drill 1 pad 1.75)
  other vias: 55.88,27.94
N$102  (via drill 1 pad 1.75)
  other vias: 55.88,25.4
N$103  (via drill 1 pad 1.75)
  other vias: 55.88,22.86
N$104  (via drill 1 pad 1.75)
  other vias: 55.88,20.32
N$105  (via drill 1 pad 1.75)
  other vias: 55.88,17.78
N$106  (via drill 1 pad 1.75)
  other vias: 55.88,15.24
N$107  (via drill 1 pad 1.75)
  other vias: 55.88,12.7
N$108  (via drill 1 pad 1.75)
  other vias: 55.88,10.16
N$109  (via drill 1 pad 1.75)
  other vias: 2.54,48.26
N$110  (via drill 1 pad 1.75)
  other vias: 10.16,17.78
N$111  (via drill 1 pad 1.75)
  other vias: 10.16,15.24
N$112  (via drill 1 pad 1.75)
  other vias: 10.16,12.7
N$113  (via drill 1 pad 1.75)
  other vias: 10.16,10.16
N$114  (via drill 1 pad 1.75)
  other vias: 10.16,7.62
N$115  (via drill 1 pad 1.75)
  other vias: 10.16,5.08
N$116  (via drill 1 pad 1.75)
  other vias: 10.16,2.54
N$117  (via drill 1 pad 1.75)
  other vias: 12.7,2.54
N$118  (via drill 1 pad 1.75)
  other vias: 15.24,2.54
N$119  (via drill 1 pad 1.75)
  other vias: 2.54,50.8
N$120  (via drill 1 pad 1.75)
  other vias: 10.16,38.1
N$121  (via drill 1 pad 1.75)
  other vias: 10.16,40.64
N$122  (via drill 1 pad 1.75)
  other vias: 10.16,43.18
N$123  (via drill 1 pad 1.75)
  other vias: 12.7,43.18
N$124  (via drill 1 pad 1.75)
  other vias: 55.88,7.62
N$125  (via drill 1 pad 1.75)
  other vias: 53.34,7.62
N$126  (via drill 1 pad 1.75)
  other vias: 50.8,7.62
N$127  (via drill 1 pad 1.75)
  other vias: 7.62,5.08
N$128  (via drill 1 pad 1.75)
  other vias: 7.62,7.62
N$129  (via drill 1 pad 1.75)
  other vias: 7.62,10.16
N$130  (via drill 1 pad 1.75)
  other vias: 7.62,12.7
N$131  (via drill 1 pad 1.75)
  other vias: 7.62,15.24
N$132  (via drill 1 pad 1.75)
  other vias: 7.62,17.78
N$133  (via drill 1 pad 1.75)
  other vias: 5.08,50.8
N$134  (via drill 1 pad 1.75)
  other vias: 5.08,48.26
N$135  (via drill 1 pad 1.75)
  other vias: 5.08,17.78
N$136  (via drill 1 pad 1.75)
  other vias: 5.08,15.24
N$137  (via drill 1 pad 1.75)
  other vias: 5.08,12.7
N$138  (via drill 1 pad 1.75)
  other vias: 5.08,10.16
N$139  (via drill 1 pad 1.75)
  other vias: 5.08,7.62
N$140  (via drill 1 pad 1.75)
  other vias: 2.54,7.62
N$141  (via drill 1 pad 1.75)
  other vias: 2.54,10.16
N$142  (via drill 1 pad 1.75)
  other vias: 2.54,12.7
N$143  (via drill 1 pad 1.75)
  other vias: 2.54,15.24
N$144  (via drill 1 pad 1.75)
  other vias: 2.54,17.78
N$145  (via drill 1 pad 1.75)
  other vias: 5.08,45.72
N$146  (via drill 1 pad 1.75)
  other vias: 12.7,45.72
N$147  (via drill 1 pad 1.75)
  other vias: 12.7,48.26
N$148  (via drill 1 pad 1.75)
  other vias: 12.7,50.8
N$149  (via drill 1 pad 1.75)
  other vias: 10.16,45.72
N$150  (via drill 1 pad 1.75)
  other vias: 10.16,48.26
N$151  (via drill 1 pad 1.75)
  other vias: 10.16,50.8
N$152  (via drill 1 pad 1.75)
  other vias: 7.62,40.64
N$153  (via drill 1 pad 1.75)
  other vias: 7.62,43.18
N$154  (via drill 1 pad 1.75)
  other vias: 7.62,45.72
N$155  (via drill 1 pad 1.75)
  other vias: 7.62,48.26
N$156  (via drill 1 pad 1.75)
  other vias: 7.62,50.8
N$157  (via drill 1 pad 1.75)
  other vias: 5.08,43.18
N$158  (via drill 1 pad 1.75)
  other vias: 7.62,38.1
N$159  (via drill 1 pad 1.75)
  other vias: 5.08,38.1
N$160  (via drill 1 pad 1.75)
  other vias: 2.54,38.1
N$161  (via drill 1 pad 1.75)
  other vias: 7.62,53.34
N$162  (via drill 1 pad 1.75)
  other vias: 5.08,53.34
N$163  (via drill 1 pad 1.75)
  other vias: 2.54,53.34
N$164  (via drill 1 pad 1.75)
  other vias: 2.54,55.88
N$165  (via drill 1 pad 1.75)
  other vias: 5.08,55.88
N$166  (via drill 1 pad 1.75)
  other vias: 7.62,55.88
N$167  (via drill 1 pad 1.75)
  other vias: 7.62,58.42
N$168  (via drill 1 pad 1.75)
  other vias: 10.16,58.42
N$169  (via drill 1 pad 1.75)
  other vias: 12.7,58.42
N$170  (via drill 1 pad 1.75)
  other vias: 5.08,58.42
N$171  (via drill 1 pad 1.75)
  other vias: 2.54,58.42
N$172  (via drill 1 pad 1.75)
  other vias: 2.54,60.96
N$173  (via drill 1 pad 1.75)
  other vias: 5.08,60.96
N$174  (via drill 1 pad 1.75)
  other vias: 7.62,60.96
N$175  (via drill 1 pad 1.75)
  other vias: 10.16,60.96
N$176  (via drill 1 pad 1.75)
  other vias: 12.7,60.96
N$177  (via drill 1 pad 1.75)
  other vias: 15.24,60.96
N$178  (via drill 1 pad 1.75)
  other vias: 7.62,2.54
N$179  (via drill 1 pad 1.75)
  other vias: 30.48,60.96
N$180  (via drill 1 pad 1.75)
  other vias: 33.02,60.96
N$181  (via drill 1 pad 1.75)
  other vias: 25.4,60.96
N$182  (via drill 1 pad 1.75)
  other vias: 27.94,60.96
TG.!RESET
  Top 0.35: X1.2.1 47.75,80.26 54.36,80.26 55.63,78.99 X2.4.1
  Bottom 0.254: X1.3.5 35.09,6.1 17.78,6.1 15.49,8.38 15.49,18.8 14.35,19.94 3.3,19.94 2.16,21.08 2.16,35.18 | 2.16,35.18 2.16,35.56 | 2.16,35.18 2.54,35.56
  Bottom 0.35: X1.2.1 44.83,83.19 12.32,83.19 1.02,71.88 1.02,36.7 2.16,35.56 2.54,35.56 X2.9.3
TG.AREF  (via drill 0.4)
  Top 0.35: X1.2.15 30.35,83.19 47.24,83.19 v48.9,81.53 X2.4.2 | v40.64,65.53 v40.64,68.07
  Bottom 0.254: v40.64,65.53 43.94,65.53 45.47,64.01 52.58,64.01 57.66,58.93 57.66,46.99 59.94,44.7 X2.10.8
  Bottom 0.35: v40.64,68.07 40.64,72.39 45.59,77.34 47.24,77.34 48.9,78.99 v48.9,81.53
TG.PB0
  Top 0.35: X1.2.26 10.41,78.99 X2.1.2
  Bottom 0.254: X2.1.1 6.6,64.52 35.05,64.52 37.59,61.98 42.93,61.98 43.94,60.96 51.05,60.96 54.61,57.4 54.61,32.26 59.94,26.92 X2.10.1
  Bottom 1: X2.1.1 X2.1.2
TG.PB1
  Bottom 0.254: X2.1.3 8.64,65.02 35.31,65.02 37.85,62.48 43.18,62.48 44.2,61.47 51.31,61.47 55.12,57.66 55.12,34.29 59.94,29.46 X2.10.2
  Bottom 0.35: X2.1.4 5.33,71.12 5.84,71.63 | 5.84,71.63 15.24,81.03 | 15.24,81.03 15.75,81.53 X1.2.25 | 15.24,81.03 15.62,81.03 16,81.41 | 5.84,71.63 5.46,71.63 5.21,71.37
  Bottom 1: X2.1.3 X2.1.4
TG.PB2
  Bottom 0.254: X2.1.5 10.67,65.53 35.56,65.53 38.1,62.99 43.43,62.99 44.45,61.98 51.56,61.98 55.63,57.91 55.63,36.32 59.94,32 X2.10.3
  Bottom 0.35: X1.2.23 17.27,80.26 17.27,78.23 16.38,77.34 13.84,77.34 X2.1.6
  Bottom 1: X2.1.5 X2.1.6
TG.PB3
  Top 0.254: X2.10.4 59.94,34.54 59.44,34.04 59.44,7.87 56.9,5.33 43.69,5.33 42.04,3.68 40.04,3.68 X1.3.4
  Bottom 0.254: X2.1.7 12.7,66.04 35.81,66.04 38.35,63.5 43.69,63.5 44.7,62.48 51.82,62.48 56.13,58.17 56.13,38.35 59.94,34.54 X2.10.4
  Bottom 0.35: X1.2.21 19.81,80.26 19.81,78.23 18.29,76.71 15.75,76.71 X2.1.8
  Bottom 1: X2.1.7 X2.1.8
TG.PB4
  Top 0.254: X2.10.5 59.94,37.08 58.93,36.07 58.93,8.13 56.64,5.84 42.2,5.84 X1.3.1
  Bottom 0.254: X2.1.9 14.73,66.55 36.07,66.55 38.61,64.01 43.94,64.01 44.96,62.99 52.07,62.99 56.64,58.42 56.64,40.39 59.94,37.08 X2.10.5
  Bottom 0.35: X1.2.19 22.35,80.26 22.35,78.23 20.19,76.07 17.65,76.07 X2.1.10
  Bottom 1: X2.1.9 X2.1.10
TG.PB5
  Top 0.254: X2.10.6 59.94,39.62 58.42,38.1 58.42,8.38 56.39,6.35 40.17,6.35 X1.3.3
  Bottom 0.254: X2.1.11 16.76,67.06 36.32,67.06 38.86,64.52 44.2,64.52 45.21,63.5 52.32,63.5 57.15,58.67 57.15,42.42 59.94,39.62 X2.10.6
  Bottom 0.35: X1.2.17 24.89,80.26 24.89,78.23 22.1,75.44 19.56,75.44 X2.1.12
  Bottom 1: X2.1.11 X2.1.12
TG.PB6
  Bottom 0.35: X2.1.14 21.46,74.8 24.51,74.8 X1.2.16
  Bottom 1: X2.1.13 X2.1.14
TG.PB7
  Bottom 0.35: X2.1.16 23.37,74.17 25.91,74.17 29.97,78.23 29.97,79.63 29.34,80.26 27.43,80.26 X1.2.18
  Bottom 1: X2.1.15 X2.1.16
TG.PC0
  Top 0.254: X2.7.1 14.99,17.78 16.26,19.05 16.26,59.44 X2.3.1
  Bottom 0.35: X1.2.13 32.51,80.26 32.51,78.23 X2.3.2
  Bottom 1: X2.3.1 X2.3.2
TG.PC1
  Top 0.254: X2.7.2 14.99,15.24 16.76,17.02 16.76,59.18 24.64,67.06 26.42,67.06 X2.3.3
  Bottom 0.35: X1.2.11 35.05,80.26 35.05,78.23 X2.3.4
  Bottom 1: X2.3.3 X2.3.4
TG.PC2
  Top 0.254: X2.7.3 14.99,12.7 17.27,14.99 17.27,58.93 24.89,66.55 28.45,66.55 X2.3.5
  Bottom 0.35: X1.2.9 37.59,80.26 37.59,78.23 X2.3.6
  Bottom 1: X2.3.5 X2.3.6
TG.PC3
  Top 0.254: X2.7.4 14.99,10.16 17.78,12.95 17.78,58.67 25.15,66.04 30.48,66.04 X2.3.7
  Bottom 0.35: X1.2.7 40.13,80.26 40.13,78.23 X2.3.8
  Bottom 1: X2.3.7 X2.3.8
TG.PC4
  Top 0.254: X2.7.5 14.99,7.62 18.29,10.92 18.29,58.42 25.4,65.53 32.51,65.53 X2.3.9
  Bottom 0.254: X2.3.9 37.59,66.55 43.69,66.55 45.72,64.52 52.83,64.52 58.17,59.18 58.17,49.02 59.94,47.24 X2.10.9
  Bottom 0.35: X1.2.5 42.67,80.26 42.67,78.23 X2.3.10
  Bottom 1: X2.3.9 X2.3.10
TG.PC5
  Top 0.254: X2.7.6 14.99,5.08 18.8,8.89 18.8,58.17 25.65,65.02 34.54,65.02 X2.3.11
  Bottom 0.254: X2.3.11 39.62,67.06 43.94,67.06 45.97,65.02 53.09,65.02 58.67,59.44 58.67,51.05 59.94,49.78 X2.10.10
  Bottom 0.35: X1.2.3 45.21,80.26 45.21,78.23 X2.3.12
  Bottom 1: X2.3.11 X2.3.12
TG.PD0
  Top 0.35: X1.2.2 53.09,78.99 X2.2.1
  Bottom 0.254: X2.2.2 60.96,63.25 68.07,56.13 68.07,50.55 66.93,49.4 66.93,8.76 63.25,5.08 X2.8.1
  Bottom 1: X2.2.2 X2.2.1
TG.PD1
  Top 0.35: X1.2.4 45.59,77.34 52.2,77.34 X2.2.3
  Bottom 0.254: X2.2.4 58.42,65.02 67.56,55.88 67.56,50.8 66.42,49.66 66.42,10.79 63.25,7.62 X2.8.2
  Bottom 1: X2.2.4 X2.2.3
TG.PD2
  Top 0.35: X1.2.6 43.69,76.71 50.29,76.71 X2.2.5
  Bottom 0.254: X2.2.6 55.88,66.8 67.06,55.63 67.06,51.05 65.91,49.91 65.91,12.83 63.25,10.16 X2.8.3
  Bottom 1: X2.2.6 X2.2.5
TG.PD3
  Top 0.35: X1.2.8 41.78,76.07 48.39,76.07 X2.2.7
  Bottom 0.254: X2.2.8 66.55,55.37 66.55,51.31 65.41,50.16 65.41,14.86 63.25,12.7 X2.8.4
  Bottom 1: X2.2.8 X2.2.7
TG.PD4
  Top 0.35: X1.2.10 39.88,75.44 46.48,75.44 X2.2.9
  Bottom 0.254: X2.2.10 52.32,67.06 54.1,67.06 66.04,55.12 66.04,51.56 64.9,50.42 64.9,16.89 63.25,15.24 X2.8.5
  Bottom 1: X2.2.10 X2.2.9
TG.PD5
  Top 0.35: X1.2.20 27.81,74.8 44.58,74.8 X2.2.11
  Bottom 0.254: X2.2.12 50.29,66.55 53.85,66.55 65.53,54.86 65.53,51.82 64.39,50.67 64.39,18.92 63.25,17.78 X2.8.6
  Bottom 1: X2.2.12 X2.2.11
TG.PD6
  Top 0.35: X1.2.22 25.91,74.17 42.67,74.17 X2.2.13
  Bottom 0.254: X2.2.14 48.26,66.04 53.59,66.04 65.02,54.61 65.02,52.07 63.88,50.93 63.88,20.95 63.25,20.32 X2.8.7
  Bottom 1: X2.2.14 X2.2.13
TG.PD7
  Top 0.35: X1.2.24 24,73.53 40.77,73.53 X2.2.15
  Bottom 0.254: X2.2.16 46.23,65.53 53.34,65.53 64.52,54.36 64.52,52.32 63.37,51.18 63.37,26.04 61.63,24.29 X2.8.8
  Bottom 1: X2.2.16 X2.2.15
TG.VCC  (via drill 0.4)
  Top 0.35: X1.2.12 32.51,80.26 9.4,80.26 1.02,71.88 1.02,37.47 1.91,36.58 v3.81,36.58
  Bottom 0.35: v3.81,36.58 10.79,36.58 11.94,37.72 | 11.94,37.72 12.32,38.1 X2.9.2 | 11.94,37.72 12.7,37.72
VCC  (via drill 0.4, 1 pad 1.75)
  Top 1.75: v5.08,22.86 v7.62,22.86 v10.16,22.86
  Bottom 0.762: 68.71,40.93 v69.06,41.27 v69.06,42.23 68.71,41.88 68.71,40.93 | 68.71,40.93 68.71,27.05 69.22,26.54 69.22,24.38 68.71,23.88 68.71,7.87 63.12,2.29 52.32,2.29 46.99,7.62 18.67,7.62 17.02,9.27 17.02,20.95 15.11,22.86 X2.9.8 11.56,22.86 11.05,22.86 | 11.05,22.86 v10.16,22.86 | 11.05,22.86 10.67,23.24 | 11.05,22.86 10.67,22.48
  Bottom 0.813: v69.06,41.27
  Bottom 1.75: v10.16,22.86 v5.08,22.86
  pour Top (no thermals): 71.91,46.35 71.91,43.18 67.47,38.73 67.47,36.04 67.31,35.88 64.45,35.88 64.29,36.04 64.29,36.83 64.45,36.99 65.72,36.99 66.04,37.31 66.04,41.43 66.83,42.23 67.94,42.23 70.64,44.77 70.64,46.36 70.8,46.51 71.75,46.51

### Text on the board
tNames: ARef | Reset | miniSTK | PB0 | PB1 | PB2 | PB3 | PB4 | PB5 | PB6 | PB7 | PC0 | PC1 | PC2 | PC3 | PC4 | PC5 | PD7 | PD6 | PD5 | PD4 | PD3 | PD2 | PD1 | PD0 | SCL | SDA | ARef | GND | 13 | 12 | IOR | RST | 11 | Addon #2 | 10 | 3V3 | 5V | 9 | 8 | GND | GND | 7 | VCC | 6 | 5 | A0 | 4 | A1 | 3 | A2 | 2 | A3 | 1 | A4 | - | + | 0 | A5 | www.leo-andres.de | GND
tStop: PCB V1.0 | 07/2013
bStop: OSHW | CC-BY-SA 3.0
